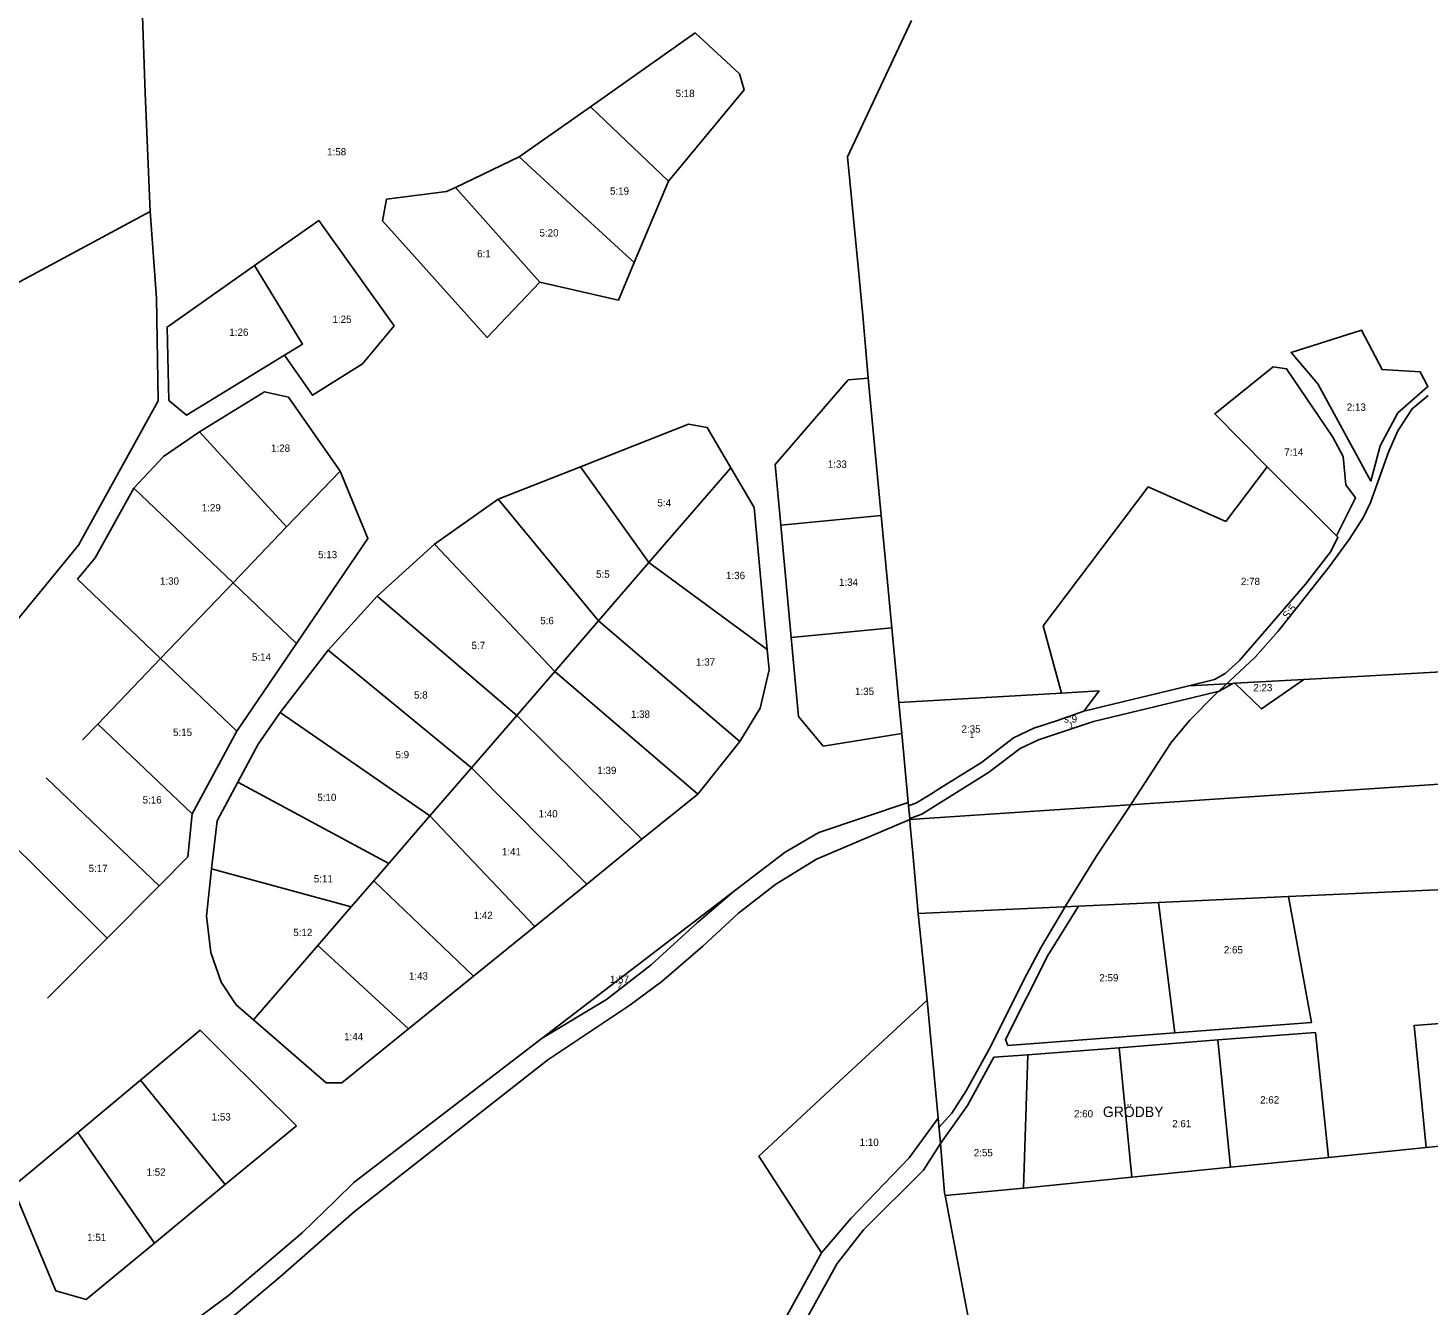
# Model space of a CAD drawing. Extents: x 140824 to 143748, y 6547319 to 6550906.
# Drawn here: x 141165 to 141835, y 6548002 to 6548613 of the extents above; entities that cross this region are included whole.
import ezdxf

# ---------------------------------------------------------------- set-up
doc = ezdxf.new("R2010")
doc.units = 0
for name, color, linetype in [('FAST Fastighetsgräns', 7, 'Continuous'), ('FAST Mittlinjeredovisad samfällighet', 7, 'Continuous'), ('FAST Områdesnummer för fastighet', 7, 'Continuous'), ('FAST Områdesnummer för samfällighet', 7, 'Continuous'), ('FAST Registernummer för fastighet', 7, 'Continuous'), ('FAST Registernummer för mittlinjeredovisad samfällighet', 7, 'Continuous'), ('FAST Registernummer för samfällighet', 7, 'Continuous'), ('FAST Traktgräns', 7, 'Continuous'), ('FAST Traktnamn', 7, 'Continuous')]:
    doc.layers.add(name, color=color, linetype=linetype)

msp = doc.modelspace()

# ---------------------------------------------------------------- linework, layer by layer
at = {"layer": 'FAST Fastighetsgräns'}
for p, q in [((141400.31, 6548551.06), (141434.31, 6548575.05)), ((141434.31, 6548575.05), (141471.6, 6548539.43)), ((141369.77, 6548536.42), (141400.31, 6548551.06)), ((141455.25, 6548500.54), (141471.6, 6548539.43)), ((141369.77, 6548536.42), (141410.17, 6548491.17)), ((141247.43, 6548419.61), (141289.06, 6548374.17)), ((141289.06, 6548374.17), (141314.68, 6548400.92)), ((141390.19, 6548387.4), (141429.59, 6548402.86)), ((141429.59, 6548402.86), (141462.28, 6548357.11)), ((141462.28, 6548357.11), (141501.43, 6548402.38)), ((141738.14, 6548376.73), (141757.78, 6548402.87)), ((141757.78, 6548402.87), (141790.96, 6548369.9)), ((141216.09, 6548392.7), (141263.49, 6548347.48)), ((141359.85, 6548365.97), (141390.19, 6548387.4)), ((141390.19, 6548387.4), (141438.17, 6548329.24)), ((141525.29, 6548375.08), (141573.35, 6548379.66)), ((141263.49, 6548347.48), (141289.06, 6548374.17)), ((141525.29, 6548375.08), (141530.32, 6548321.34)), ((141332.38, 6548341.03), (141359.85, 6548365.97)), ((141359.85, 6548365.97), (141417.31, 6548305.13)), ((141438.17, 6548329.24), (141462.28, 6548357.11)), ((141462.28, 6548357.11), (141518.88, 6548315.63)), ((141189.17, 6548349.19), (141228.86, 6548311.32)), ((141228.86, 6548311.32), (141263.49, 6548347.48)), ((141263.49, 6548347.48), (141293.86, 6548318.51)), ((141309.01, 6548315.24), (141332.38, 6548341.03)), ((141332.38, 6548341.03), (141399.07, 6548284.02)), ((141417.31, 6548305.13), (141438.17, 6548329.24)), ((141438.17, 6548329.24), (141505.67, 6548271.62)), ((141530.32, 6548321.34), (141578.43, 6548325.91)), ((141265.3, 6548276.5), (141293.86, 6548318.51)), ((142163.49, 6548322.6), (141775.28, 6548301.31)), ((141198.81, 6548279.94), (141228.86, 6548311.32)), ((141228.86, 6548311.32), (141265.3, 6548276.5)), ((141285.93, 6548285.52), (141309.01, 6548315.24)), ((141309.01, 6548315.24), (141377.46, 6548259.05)), ((141399.07, 6548284.02), (141417.31, 6548305.13)), ((141417.31, 6548305.13), (141485.58, 6548246.45)), ((141670.24, 6548286.08), (141720.37, 6548298.2)), ((141732.61, 6548301.16), (141720.37, 6548298.2)), ((141720.37, 6548298.2), (141741.34, 6548299.39)), ((141741.34, 6548299.39), (141742.33, 6548299.44)), ((141742.33, 6548299.44), (141775.28, 6548301.31)), ((141659.48, 6548294.76), (141581.82, 6548290.29)), ((141677.48, 6548295.76), (141659.48, 6548294.76)), ((141670.24, 6548286.08), (141677.48, 6548295.76)), ((141285.93, 6548285.52), (141357.55, 6548236.02)), ((141377.46, 6548259.05), (141399.07, 6548284.02)), ((141399.07, 6548284.02), (141458.96, 6548224.83)), ((141191.51, 6548272.32), (141198.81, 6548279.94)), ((141198.81, 6548279.94), (141243.99, 6548236.97)), ((141243.99, 6548236.97), (141265.3, 6548276.5)), ((141485.58, 6548246.45), (141505.67, 6548271.62)), ((141587.01, 6548234.32), (142172.85, 6548273.2)), ((141357.55, 6548236.02), (141377.46, 6548259.05)), ((141377.46, 6548259.05), (141432.61, 6548203.43)), ((141174.17, 6548254.22), (141228.14, 6548202.51)), ((141265.78, 6548252.09), (141337.91, 6548213.31)), ((141458.96, 6548224.83), (141485.58, 6548246.45)), ((141337.91, 6548213.31), (141357.55, 6548236.02)), ((141357.55, 6548236.02), (141407.68, 6548183.18)), ((141586.97, 6548234.3), (141587.01, 6548234.32)), ((141150.7, 6548229.72), (141203.32, 6548177.56)), ((141432.61, 6548203.43), (141458.96, 6548224.83)), ((141503.19, 6548200.16), (141527.43, 6548218.74)), ((141253.23, 6548210.64), (141319.9, 6548192.49)), ((141330.74, 6548205.03), (141337.91, 6548213.31)), ((141319.9, 6548192.49), (141330.74, 6548205.03)), ((141330.74, 6548205.03), (141378.36, 6548159.37)), ((141407.68, 6548183.18), (141432.61, 6548203.43)), ((141203.32, 6548177.56), (141228.14, 6548202.51)), ((141411.32, 6548129.75), (141503.19, 6548200.16)), ((141705.84, 6548194.61), (141768.09, 6548197.47)), ((141303.96, 6548174.07), (141319.9, 6548192.49)), ((141667.56, 6548192.86), (141705.84, 6548194.61)), ((141713.73, 6548132.32), (141705.84, 6548194.61)), ((141174.82, 6548148.81), (141203.32, 6548177.56)), ((141378.36, 6548159.37), (141407.68, 6548183.18)), ((141273.21, 6548138.47), (141303.96, 6548174.07)), ((141303.96, 6548174.07), (141347.37, 6548134.21)), ((141347.37, 6548134.21), (141378.36, 6548159.37)), ((141595.22, 6548147.96), (141553.24, 6548108.96)), ((141219.18, 6548109.68), (141247.77, 6548133.5)), ((141321.2, 6548060.67), (141411.32, 6548129.75)), ((141687.02, 6548125.15), (141693.09, 6548063.21)), ((141734.31, 6548128.91), (141740.3, 6548067.99)), ((141643.44, 6548121.83), (141641.27, 6548057.98)), ((141189.2, 6548084.7), (141219.18, 6548109.68)), ((141219.18, 6548109.68), (141259.77, 6548059.79)), ((141189.2, 6548084.7), (141225.85, 6548031.79)), ((141293.8, 6548087.87), (141259.77, 6548059.79)), ((141225.85, 6548031.79), (141259.77, 6548059.79))]:
    msp.add_line(p, q, dxfattribs=at)
for points in [[(141471.6, 6548539.43), (141507.88, 6548583.14), (141505.56, 6548590.83), (141484.41, 6548610.38), (141434.31, 6548575.05)], [(141400.31, 6548551.06), (141428.82, 6548524.89), (141455.25, 6548500.54)], [(141410.17, 6548491.17), (141384.92, 6548464.78), (141334.89, 6548520.61), (141336.8, 6548530.88), (141365.51, 6548534.62), (141369.77, 6548536.42)], [(140824.31, 6548245.73), (140834.06, 6548254.02), (140876.79, 6548290.01), (141033.16, 6548422.33), (141223.91, 6548524.98)], [(141288.09, 6548456.35), (141301.39, 6548437.13), (141325.4, 6548452.22), (141340.45, 6548470.32), (141304.42, 6548520.63), (141273.75, 6548499.12)], [(141288.09, 6548456.35), (141241.24, 6548427.55), (141232.84, 6548434.65), (141231.97, 6548469.75), (141273.75, 6548499.12)], [(141288.09, 6548456.35), (141296.61, 6548461.56), (141273.75, 6548499.12)], [(141410.17, 6548491.17), (141447.75, 6548482.63), (141455.25, 6548500.54)], [(141807.4, 6548396.05), (141782, 6548442.65), (141769.25, 6548457.61), (141802.93, 6548468.2), (141812.73, 6548449.44), (141830.92, 6548448.38), (141834.71, 6548441.27), (141820.35, 6548428.68), (141811.89, 6548412.92), (141807.4, 6548396.05)], [(141525.29, 6548375.08), (141522.58, 6548404.04), (141557.58, 6548444.48), (141567.15, 6548445.37)], [(141790.96, 6548369.9), (141800.02, 6548388.14), (141795.4, 6548394.38), (141794.1, 6548407.81), (141789.2, 6548417.1), (141767.11, 6548449.83), (141760.66, 6548450.72), (141732.76, 6548428.27), (141757.78, 6548402.87)], [(141247.43, 6548419.61), (141278.53, 6548438.71), (141289.99, 6548436.15), (141314.68, 6548400.92)], [(141216.09, 6548392.7), (141230.21, 6548407.93), (141247.43, 6548419.61)], [(141429.59, 6548402.86), (141481.14, 6548423.35), (141490.15, 6548421.73), (141501.43, 6548402.38)], [(141293.86, 6548318.51), (141327.94, 6548368.62), (141314.68, 6548400.92)], [(141501.43, 6548402.38), (141512.53, 6548383.49), (141518.88, 6548315.63)], [(141189.17, 6548349.19), (141197.61, 6548359.45), (141216.09, 6548392.7)], [(141738.14, 6548376.73), (141700.96, 6548393.41), (141650.77, 6548326.9), (141659.48, 6548294.76)], [(141788.33, 6548362.44), (141791.63, 6548369.24), (141790.96, 6548369.9)], [(141788.33, 6548362.44), (141776.16, 6548346.76), (141744.58, 6548310.39), (141737.68, 6548304.09), (141732.61, 6548301.16)], [(141530.32, 6548321.34), (141533.85, 6548283.61), (141545.61, 6548269.33), (141583.21, 6548275.34)], [(141505.67, 6548271.62), (141515.43, 6548287.59), (141519.74, 6548305.84), (141518.88, 6548315.63)], [(141586.93, 6548234.69), (141587.52, 6548234.91), (141592.8, 6548236.87), (141624.62, 6548256.77), (141639.67, 6548268.26), (141648.46, 6548272.45), (141659.46, 6548275.98), (141674.88, 6548281.09), (141721.76, 6548292.42), (141734.84, 6548295.59), (141741.34, 6548299.39)], [(141775.28, 6548301.31), (141755.05, 6548287.14), (141742.33, 6548299.44)], [(141265.78, 6548252.09), (141275.55, 6548270.25), (141285.93, 6548285.52)], [(141586.93, 6548234.69), (141586.4, 6548240.79), (141590.19, 6548242.19), (141596.28, 6548246), (141597.51, 6548246.77), (141602.5, 6548249.89), (141605.28, 6548251.63), (141621.26, 6548261.62), (141636.57, 6548273.32), (141646.28, 6548277.95), (141657.57, 6548281.57), (141670.24, 6548286.08)], [(141253.23, 6548210.64), (141255.82, 6548233.62), (141265.78, 6548252.09)], [(141228.14, 6548202.51), (141241.84, 6548216.4), (141243.99, 6548236.97)], [(141527.43, 6548218.74), (141543.45, 6548228.15), (141586.25, 6548242.38)], [(140980.52, 6547910.3), (140990.98, 6547909.95), (141033.02, 6547907.12), (141056.85, 6547907.1), (141074.94, 6547908.7), (141090.36, 6547911.46), (141112.78, 6547918.14), (141181.19, 6547944.15), (141194.83, 6547950.24), (141214.56, 6547960.98), (141234.26, 6547974.33), (141264.91, 6547997.93), (141285.93, 6548015.65), (141321.46, 6548046.93), (141413.91, 6548119.44), (141453.09, 6548145.51), (141468.41, 6548156.81), (141488.02, 6548173.66), (141505.13, 6548189.58), (141522.91, 6548203.37), (141542.31, 6548215.28), (141586.97, 6548234.3)], [(141273.21, 6548138.47), (141264.88, 6548145.7), (141257.83, 6548156.49), (141252.82, 6548170.63), (141250.73, 6548188), (141253.23, 6548210.64)], [(141411.32, 6548129.75), (141441.95, 6548148.16), (141463.37, 6548164.87), (141485.35, 6548184.88), (141503.19, 6548200.16)], [(141273.21, 6548138.47), (141307.92, 6548108.43), (141315.52, 6548108.34), (141347.37, 6548134.21)], [(141247.77, 6548133.5), (141259.12, 6548122.22), (141293.8, 6548087.87)], [(141553.24, 6548108.96), (141514.81, 6548073.25), (141544.82, 6548027.04)], [(141544.82, 6548027.04), (141558.78, 6548043.47), (141586.64, 6548072.5), (141600.47, 6548091.51)], [(141225.85, 6548031.79), (141193.22, 6548004.85), (141178.81, 6548008.98), (141157.98, 6548058.69), (141189.2, 6548084.7)], [(141296.63, 6548036.78), (141312.39, 6548052.12), (141321.2, 6548060.67)], [(141184.36, 6547955.19), (141208.02, 6547967.36), (141261.24, 6548006.65), (141296.63, 6548036.78)], [(141544.82, 6548027.04), (141524.07, 6547989.44), (141502.21, 6547956.52)]]:
    msp.add_lwpolyline(points, dxfattribs=at)
at = {"layer": 'FAST Mittlinjeredovisad samfällighet'}
msp.add_lwpolyline([(141600.85, 6548087.06), (141607.01, 6548093.83), (141613.92, 6548104.63), (141625.68, 6548125.85), (141641.56, 6548157.66), (141649.78, 6548173.26), (141661.96, 6548193.59), (141676.42, 6548217.08), (141690.84, 6548238.8), (141711.86, 6548271.05), (141720.83, 6548281.79), (141732.62, 6548293.77), (141752.06, 6548311.98), (141763.12, 6548324.27), (141776.06, 6548340.62), (141787.48, 6548355.1), (141797.41, 6548368.6), (141803.86, 6548378.82), (141807.15, 6548385.92), (141815.76, 6548409.87), (141820.31, 6548420.15), (141827.07, 6548430.66), (141834.73, 6548437.04)], dxfattribs=at)
at = {"layer": 'FAST Traktgräns'}
for p, q in [((141221.44, 6548581.59), (141218.75, 6548659.28)), ((141587.74, 6548616.33), (141557.13, 6548551.18)), ((141223.91, 6548524.98), (141221.44, 6548581.59)), ((141557.13, 6548551.18), (141562.55, 6548495.43)), ((141562.55, 6548495.43), (141564.51, 6548475.24)), ((141567.15, 6548445.37), (141564.51, 6548475.24)), ((141567.15, 6548445.37), (141573.35, 6548379.66)), ((141573.35, 6548379.66), (141578.43, 6548325.91)), ((141578.43, 6548325.91), (141581.82, 6548290.29)), ((141581.82, 6548290.29), (141583.21, 6548275.34)), ((141583.21, 6548275.34), (141586.25, 6548242.38)), ((141586.25, 6548242.38), (141586.93, 6548234.69)), ((141586.93, 6548234.69), (141586.97, 6548234.31)), ((141586.97, 6548234.31), (141586.97, 6548234.3)), ((141586.97, 6548234.3), (141587.23, 6548231.36)), ((141587.23, 6548231.36), (141588.4, 6548218.18)), ((141588.4, 6548218.18), (141590.96, 6548189.35)), ((141768.09, 6548197.47), (141989.34, 6548207.6)), ((141590.96, 6548189.35), (141667.56, 6548192.86)), ((141590.96, 6548189.35), (141595.22, 6548147.96)), ((141595.22, 6548147.96), (141600.47, 6548091.51)), ((141643.44, 6548121.83), (141687.02, 6548125.15)), ((141687.02, 6548125.15), (141734.31, 6548128.91)), ((141600.47, 6548091.51), (141601.6, 6548079.32)), ((141603.51, 6548055.85), (141601.6, 6548079.32)), ((141833.88, 6548077.44), (141787.21, 6548072.73)), ((141862.77, 6548080.36), (141833.88, 6548077.44)), ((141787.21, 6548072.73), (141740.3, 6548067.99)), ((141693.09, 6548063.21), (141641.27, 6548057.98)), ((141740.3, 6548067.99), (141693.09, 6548063.21)), ((141641.27, 6548057.98), (141603.86, 6548054.53)), ((141603.51, 6548055.85), (141603.86, 6548054.53)), ((141603.86, 6548054.53), (141627.57, 6547929.89))]:
    msp.add_line(p, q, dxfattribs=at)
for points in [[(141062.72, 6548242.22), (141081.63, 6548251.76), (141110.67, 6548269.43), (141189.64, 6548365.4), (141227.74, 6548434.45), (141226.93, 6548483.57), (141223.91, 6548524.98)], [(141768.09, 6548197.47), (141779.05, 6548137.3), (141713.73, 6548132.32)], [(141713.73, 6548132.32), (141633.88, 6548126.25), (141632.72, 6548129.08), (141652.91, 6548169.25), (141667.56, 6548192.86)], [(141833.88, 6548077.44), (141828.06, 6548135.85), (141857.05, 6548138.01)], [(141734.31, 6548128.91), (141780.94, 6548132.37), (141787.21, 6548072.73)], [(141601.6, 6548079.32), (141614.59, 6548097.58), (141627.19, 6548120.59), (141643.44, 6548121.83)], [(141601.6, 6548079.32), (141593.5, 6548066.61), (141564.93, 6548038.08), (141552.23, 6548022.07), (141531.87, 6547985.14)]]:
    msp.add_lwpolyline(points, dxfattribs=at)

# ---------------------------------------------------------------- texts
at = {"layer": 'FAST Områdesnummer för fastighet'}
for s, p in [('1', (141615.74, 6548273.32)), ('2', (141447.44, 6548153.64))]:
    msp.add_text(s, height=2.5, dxfattribs=at).set_placement(p)
at = {"layer": 'FAST Områdesnummer för samfällighet'}
msp.add_text('1', height=2.5, dxfattribs=at).set_placement((141663.22, 6548278.13))
at = {"layer": 'FAST Registernummer för fastighet'}
for s, p in [('5:18', (141475.02, 6548579.72)), ('1:58', (141308.42, 6548551.83)), ('5:19', (141443.66, 6548533.03)), ('5:20', (141409.97, 6548513.03)), ('6:1', (141380.14, 6548503.05)), ('1:25', (141311.01, 6548471.72)), ('1:26', (141261.7, 6548465.52)), ('2:13', (141795.89, 6548429.71)), ('1:28', (141281.61, 6548410.09)), ('7:14', (141766, 6548408.23)), ('1:33', (141547.78, 6548402.46)), ('1:29', (141248.51, 6548381.62)), ('5:4', (141466.37, 6548383.95)), ('5:13', (141304.13, 6548359.22)), ('5:5', (141437.01, 6548349.87)), ('1:36', (141499.13, 6548349.22)), ('1:30', (141228.51, 6548346.57)), ('1:34', (141553.14, 6548346.01)), ('2:78', (141745.28, 6548346.39)), ('5:6', (141410.32, 6548327.66)), ('5:7', (141377.47, 6548315.75)), ('5:14', (141272.51, 6548310.24)), ('1:37', (141484.79, 6548307.85)), ('1:35', (141560.79, 6548293.81)), ('2:23', (141751.21, 6548295.59)), ('5:8', (141349.99, 6548292.12)), ('1:38', (141453.66, 6548282.9)), ('5:15', (141234.77, 6548274.22)), ('2:35', (141611.73, 6548275.82)), ('5:9', (141341.12, 6548263.56)), ('1:39', (141437.63, 6548256.01)), ('5:16', (141220.24, 6548241.94)), ('5:10', (141303.75, 6548243.1)), ('1:40', (141409.54, 6548235.29)), ('1:41', (141391.97, 6548217.12)), ('5:17', (141194.41, 6548209.17)), ('5:11', (141302.08, 6548204.2)), ('1:42', (141378.51, 6548186.72)), ('5:12', (141292.26, 6548178.54)), ('2:65', (141737.12, 6548170.25)), ('1:43', (141347.53, 6548157.72)), ('1:57', (141443.67, 6548156.14)), ('2:59', (141677.62, 6548156.88)), ('1:44', (141316.57, 6548128.73)), ('2:62', (141754.45, 6548098.49)), ('1:53', (141253.27, 6548090.36)), ('2:60', (141665.49, 6548091.85)), ('2:61', (141712.42, 6548087.13)), ('1:10', (141563.03, 6548078.21)), ('2:55', (141617.57, 6548073.23)), ('1:52', (141222.12, 6548063.97)), ('1:51', (141193.7, 6548032.74))]:
    msp.add_text(s, height=3.5, dxfattribs=at).set_placement(p)
at = {"layer": 'FAST Registernummer för mittlinjeredovisad samfällighet'}
msp.add_text('S:5', height=3.5, rotation=51.749, dxfattribs=at).set_placement((141767.59, 6548329.9))
at = {"layer": 'FAST Registernummer för samfällighet'}
msp.add_text('s:9', height=3.5, dxfattribs=at).set_placement((141660.71, 6548280.63))
at = {"layer": 'FAST Traktnamn'}
msp.add_text('GRÖDBY', height=5, dxfattribs=at).set_placement((141679.29, 6548092.04))

doc.saveas('drawing.dxf')
